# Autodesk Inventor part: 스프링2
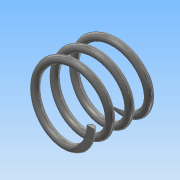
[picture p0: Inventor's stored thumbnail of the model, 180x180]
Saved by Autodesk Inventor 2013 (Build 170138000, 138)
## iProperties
Created: 2016-10
Part Number: 스프링2
Material: 강철, 탄소
Document SubType Name: Modeling
Designer: Administrator
Mass: 6.67678 g
Surface Area: 17.4315 cm^2
Volume: 0.848384 cm^3
Density: 7.87 g/cm^3
Author: Administrator
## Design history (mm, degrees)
sketch "스케치1"
  geometry: L1 (0, 0)-(0, 26); L2 (0, 26)-(25, 26); C1 r 1 at (9, 0)
  constraints: 4 end point, 1 centre point, 1 horizontal alignment, 1 perpendicular, 1 vertical
  dimensions: "d0" = 26 distance of L1.start L1.end (derived); "d1" = 25 distance of L1.end L2.end; "d2" = 2 diameter of C1; "d3" = 18 diameter of C1.centre L1
feature "코일1" sketch "스케치1" pitch "d4" = 10; turns "d6" = 5; dims "d5" = 27, "d7" = 0, angle "d8" = 90 deg, angle "d9" = 90 deg, "d10" = 0, "d11" = 0
sketch "스케치2"
  geometry: L1 (26, 12)-(0, 12); L2 (0, 12)-(0, -12); L3 (0, -12)-(26, -12); L4 (26, -12)-(26, 12); 2 further points
  constraints: 8 end point, 2 parallel, 1 coincident, 1 horizontal, 1 midpoint, 1 perpendicular
  dimensions: "d12" = 26 distance of L1.start L1.end (derived); "d14" = 24 distance of L3.end L1.start
extrude "돌출1" sketch "스케치2" stored distance "d15" = 0; taper "d16" = 0 deg
node "솔리드1"
